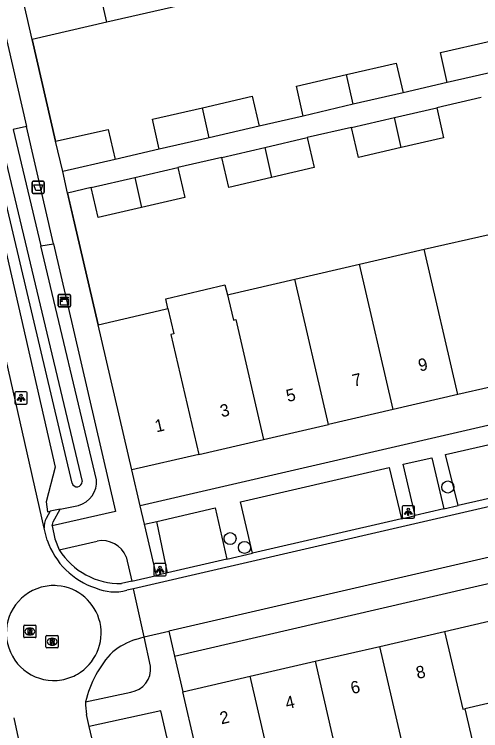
# Model space of a CAD drawing. Extents: x 156414 to 157775, y 382335 to 383765.
# Drawn here: x 156749.8 to 156787.7, y 382552.8 to 382611 of the extents above; entities that cross this region are included whole.
import ezdxf

# ---------------------------------------------------------------- set-up
doc = ezdxf.new("R2010")
doc.units = 0
for name, color, linetype in [('IMGEO_Afvalbak', 7, 'Continuous'), ('IMGEO_Berm_groen', 7, 'Continuous'), ('IMGEO_Boom', 7, 'Continuous'), ('IMGEO_Greppel_droge_sloot', 7, 'Continuous'), ('IMGEO_Haag', 7, 'Continuous'), ('IMGEO_Kast', 7, 'Continuous'), ('IMGEO_Lichtpunt', 7, 'Continuous'), ('IMGEO_Muur', 7, 'Continuous'), ('IMGEO_Pand', 7, 'Continuous'), ('IMGEO_Pand_nummerreeks', 7, 'Continuous'), ('IMGEO_Rijbaan_lokaal_gesloten', 7, 'Continuous'), ('IMGEO_Rijbaan_lokaal_open', 7, 'Continuous'), ('IMGEO_Rioolput', 7, 'Continuous'), ('IMGEO_Voetpad_open', 7, 'Continuous')]:
    doc.layers.add(name, color=color, linetype=linetype)

msp = doc.modelspace()

# ---------------------------------------------------------------- linework, layer by layer
at = {"layer": 'IMGEO_Afvalbak'}
for p, q in [((156751.392, 382597.403), (156752.182, 382597.403)), ((156752.182, 382597.403), (156751.392, 382597.403)), ((156751.292, 382596.503), (156751.292, 382597.303)), ((156751.292, 382597.303), (156751.292, 382596.503)), ((156752.282, 382597.303), (156752.282, 382596.503)), ((156752.282, 382596.503), (156752.282, 382597.303)), ((156752.182, 382596.403), (156751.392, 382596.403)), ((156751.392, 382596.403), (156752.182, 382596.403))]:
    msp.add_line(p, q, dxfattribs=at)
msp.add_lwpolyline([(156751.435, 382597.117), (156752.139, 382597.117), (156751.99, 382596.647), (156751.584, 382596.647), (156751.435, 382597.117)], dxfattribs=at)
for centre, start, end in [((156751.392, 382597.303), 90, 180), ((156751.392, 382597.303), 90, 180), ((156752.182, 382597.303), 0, 90), ((156752.182, 382597.303), 360, 90), ((156751.392, 382596.503), 180, 270), ((156751.392, 382596.503), 180, 270), ((156752.182, 382596.503), 270, 0), ((156752.182, 382596.503), 270, 0)]:
    msp.add_arc(centre, 0.1, start, end, dxfattribs=at)
at = {"layer": 'IMGEO_Berm_groen'}
for points in [[(156742.922, 382618.934), (156753.154, 382574.176), (156752.429, 382571.339), (156752.537, 382570.534), (156752.762, 382570.58)], [(156756.533, 382573.152), (156752.001, 382592.15)], [(156753.579, 382570.748), (156755.068, 382571.054)]]:
    msp.add_lwpolyline(points, dxfattribs=at)
msp.add_arc((156754.477, 382573.027), 2.059, 286.66477, 3.48327, dxfattribs=at)
at = {"layer": 'IMGEO_Boom'}
for centre in [(156785.07, 382572.555), (156767.379, 382568.36), (156768.551, 382567.646)]:
    msp.add_circle(centre, 0.489, dxfattribs=at)
at = {"layer": 'IMGEO_Greppel_droge_sloot'}
for points in [[(156754.54, 382572.878), (156743.906, 382617.872)], [(156744.672, 382617.996), (156748.601, 382601.316), (156750.852, 382591.876), (156755.355, 382572.999)]]:
    msp.add_lwpolyline(points, dxfattribs=at)
msp.add_arc((156754.94, 382572.988), 0.415, 195.34481, 1.54479, dxfattribs=at)
at = {"layer": 'IMGEO_Haag'}
for points in [[(156750.838, 382601.836), (156749.75, 382601.59)], [(156749.75, 382601.59), (156752.001, 382592.15)], [(156752.001, 382592.15), (156753.038, 382592.306)]]:
    msp.add_lwpolyline(points, dxfattribs=at)
at = {"layer": 'IMGEO_Kast'}
for p, q in [((156753.418, 382587.273), (156753.418, 382588.114)), ((156753.418, 382588.114), (156753.418, 382587.273)), ((156753.493, 382588.198), (156754.334, 382588.198)), ((156754.334, 382588.198), (156753.493, 382588.198)), ((156754.418, 382588.123), (156754.418, 382587.282)), ((156754.418, 382587.282), (156754.418, 382588.123)), ((156754.343, 382587.198), (156753.502, 382587.198)), ((156753.502, 382587.198), (156754.343, 382587.198))]:
    msp.add_line(p, q, dxfattribs=at)
for points in [[(156753.613, 382587.988), (156754.213, 382587.988), (156754.213, 382587.903), (156753.613, 382587.903), (156753.613, 382587.988)], [(156753.613, 382587.813), (156754.213, 382587.813), (156754.213, 382587.324), (156753.613, 382587.324), (156753.613, 382587.813)]]:
    msp.add_lwpolyline(points, dxfattribs=at)
msp.add_circle((156753.697, 382587.662), 0.0377, dxfattribs=at)
for centre, start, end in [((156753.496, 382588.12), 92.4484, 184.28452), ((156753.496, 382588.12), 92.4484, 184.28452), ((156754.34, 382588.12), 2.4484, 94.28452), ((156754.34, 382588.12), 2.4484, 94.28452), ((156753.496, 382587.276), 182.4484, 274.28452), ((156753.496, 382587.276), 182.4484, 274.28452), ((156754.34, 382587.276), 272.4484, 4.28452), ((156754.34, 382587.276), 272.4484, 4.28452)]:
    msp.add_arc(centre, 0.0779, start, end, dxfattribs=at)
at = {"layer": 'IMGEO_Lichtpunt'}
for p, q in [((156749.883, 382580.198), (156749.883, 382579.391)), ((156749.883, 382580.198), (156749.883, 382579.391)), ((156750.785, 382580.293), (156749.977, 382580.293)), ((156750.785, 382580.293), (156749.977, 382580.293)), ((156750.879, 382579.391), (156750.879, 382580.198)), ((156750.879, 382579.391), (156750.879, 382580.198)), ((156749.977, 382579.297), (156750.785, 382579.297)), ((156749.977, 382579.297), (156750.785, 382579.297)), ((156781.352, 382570.938), (156781.352, 382570.131)), ((156781.352, 382570.938), (156781.352, 382570.131)), ((156782.254, 382571.033), (156781.446, 382571.033)), ((156782.254, 382571.033), (156781.446, 382571.033)), ((156782.348, 382570.131), (156782.348, 382570.938)), ((156782.348, 382570.131), (156782.348, 382570.938)), ((156781.446, 382570.037), (156782.254, 382570.037)), ((156781.446, 382570.037), (156782.254, 382570.037)), ((156761.191, 382566.233), (156761.191, 382565.426)), ((156761.191, 382566.233), (156761.191, 382565.426)), ((156762.093, 382566.328), (156761.285, 382566.328)), ((156762.093, 382566.328), (156761.285, 382566.328)), ((156762.187, 382565.426), (156762.187, 382566.233)), ((156762.187, 382565.426), (156762.187, 382566.233)), ((156761.285, 382565.332), (156762.093, 382565.332)), ((156761.285, 382565.332), (156762.093, 382565.332))]:
    msp.add_line(p, q, dxfattribs=at)
for points in [[(156750.257, 382579.862), (156750.296, 382579.834), (156750.108, 382579.572), (156750.07, 382579.599), (156750.257, 382579.862)], [(156750.469, 382579.834), (156750.507, 382579.861), (156750.694, 382579.599), (156750.655, 382579.571), (156750.469, 382579.834)], [(156750.359, 382579.814), (156750.406, 382579.814), (156750.406, 382579.492), (156750.359, 382579.492), (156750.359, 382579.814)], [(156781.726, 382570.602), (156781.765, 382570.574), (156781.577, 382570.312), (156781.539, 382570.339), (156781.726, 382570.602)], [(156781.828, 382570.554), (156781.875, 382570.554), (156781.875, 382570.232), (156781.828, 382570.232), (156781.828, 382570.554)], [(156781.938, 382570.574), (156781.976, 382570.601), (156782.163, 382570.339), (156782.124, 382570.311), (156781.938, 382570.574)], [(156761.565, 382565.897), (156761.604, 382565.869), (156761.416, 382565.607), (156761.378, 382565.634), (156761.565, 382565.897)], [(156761.777, 382565.869), (156761.815, 382565.896), (156762.002, 382565.634), (156761.963, 382565.606), (156761.777, 382565.869)], [(156761.667, 382565.849), (156761.714, 382565.849), (156761.714, 382565.527), (156761.667, 382565.527), (156761.667, 382565.849)]]:
    msp.add_lwpolyline(points, dxfattribs=at)
for centre in [(156750.382, 382579.996), (156781.851, 382570.736), (156761.69, 382566.031)]:
    msp.add_circle(centre, 0.0994, dxfattribs=at)
for centre, start, end in [((156749.977, 382580.198), 90, 180), ((156749.977, 382580.198), 90, 180), ((156750.785, 382580.198), 0, 90), ((156750.785, 382580.198), 0, 90), ((156749.977, 382579.391), 180, 270), ((156749.977, 382579.391), 180, 270), ((156750.785, 382579.391), 270, 0), ((156750.785, 382579.391), 270, 360), ((156781.446, 382570.938), 90, 180), ((156781.446, 382570.938), 90, 180), ((156782.254, 382570.938), 0, 90), ((156782.254, 382570.938), 0, 90), ((156781.446, 382570.131), 180, 270), ((156781.446, 382570.131), 180, 270), ((156782.254, 382570.131), 270, 0), ((156782.254, 382570.131), 270, 360), ((156761.285, 382566.233), 90, 180), ((156761.285, 382566.233), 90, 180), ((156762.093, 382566.233), 0, 90), ((156762.093, 382566.233), 0, 90), ((156761.285, 382565.426), 180, 270), ((156761.285, 382565.426), 180, 270), ((156762.093, 382565.426), 270, 0), ((156762.093, 382565.426), 270, 360)]:
    msp.add_arc(centre, 0.0946, start, end, dxfattribs=at)
at = {"layer": 'IMGEO_Muur'}
for points in [[(156751.301, 382608.917), (156753.206, 382600.657)], [(156754.739, 382594), (156754.172, 382596.455)], [(156756.65, 382585.734), (156754.739, 382594)]]:
    msp.add_lwpolyline(points, dxfattribs=at)
at = {"layer": 'IMGEO_Pand'}
for points in [[(156751.301, 382608.917), (156747.906, 382623.621)], [(156757.366, 382610.315), (156754.657, 382622.088)], [(156763.216, 382611.663), (156757.366, 382610.315)], [(156757.366, 382610.315), (156751.301, 382608.917)], [(156785.022, 382605.412), (156784.459, 382607.848), (156788.515, 382608.786)], [(156776.837, 382606.076), (156780.864, 382607.006), (156781.434, 382604.572)], [(156773.325, 382602.699), (156772.762, 382605.135), (156776.837, 382606.076)], [(156777.379, 382603.65), (156776.837, 382606.076)], [(156789.066, 382606.348), (156785.022, 382605.412)], [(156765.136, 382603.374), (156769.174, 382604.304), (156769.738, 382601.869)], [(156781.434, 382604.572), (156777.379, 382603.65)], [(156761.629, 382600), (156761.068, 382602.436), (156765.136, 382603.374)], [(156765.677, 382600.933), (156765.136, 382603.374)], [(156777.379, 382603.65), (156773.325, 382602.699)], [(156780.723, 382602.572), (156784.164, 382603.368)], [(156784.164, 382603.368), (156784.72, 382600.931), (156781.268, 382600.132)], [(156777.243, 382601.766), (156780.723, 382602.572)], [(156781.268, 382600.132), (156780.723, 382602.572)], [(156753.206, 382600.657), (156757.462, 382601.592), (156758.032, 382599.158)], [(156769.738, 382601.869), (156765.677, 382600.933)], [(156781.268, 382600.132), (156777.807, 382599.331), (156777.243, 382601.766)], [(156765.677, 382600.933), (156761.629, 382600)], [(156770.19, 382600.141), (156773.639, 382600.94)], [(156773.639, 382600.94), (156774.198, 382598.503), (156770.736, 382597.701)], [(156753.785, 382598.18), (156753.206, 382600.657)], [(156766.717, 382599.337), (156770.19, 382600.141)], [(156770.19, 382600.141), (156770.736, 382597.701)], [(156758.032, 382599.158), (156753.785, 382598.18)], [(156770.736, 382597.701), (156767.281, 382596.901), (156766.717, 382599.337)], [(156759.63, 382597.697), (156763.126, 382598.503)], [(156763.126, 382598.503), (156763.691, 382596.068), (156760.177, 382595.258)], [(156756.097, 382596.883), (156759.63, 382597.697)], [(156759.63, 382597.697), (156760.177, 382595.258)], [(156760.177, 382595.258), (156756.658, 382594.447), (156756.097, 382596.883)], [(156783.154, 382591.87), (156788.417, 382593.085)], [(156777.894, 382590.654), (156783.154, 382591.87)], [(156785.883, 382580.062), (156783.154, 382591.87)], [(156772.632, 382589.438), (156777.894, 382590.654)], [(156780.621, 382578.847), (156777.894, 382590.654)], [(156767.174, 382588.177), (156767.381, 382588.225), (156772.632, 382589.438)], [(156775.36, 382577.632), (156772.632, 382589.438)], [(156762.333, 382587.053), (156762.147, 382587.853), (156766.962, 382588.971), (156767.174, 382588.177)], [(156767.174, 382588.177), (156767.259, 382587.811), (156767.651, 382586.122), (156767.854, 382586.169), (156770.098, 382576.416)], [(156756.65, 382585.734), (156762.096, 382586.998), (156762.333, 382587.053)], [(156762.333, 382587.053), (156762.81, 382584.998), (156762.573, 382584.943), (156764.837, 382575.201)], [(156759.384, 382573.942), (156756.65, 382585.734)], [(156791.144, 382581.277), (156785.883, 382580.062)], [(156785.883, 382580.062), (156780.621, 382578.847)], [(156780.621, 382578.847), (156775.36, 382577.632)], [(156770.098, 382576.416), (156775.36, 382577.632)], [(156764.837, 382575.201), (156770.098, 382576.416)], [(156764.837, 382575.201), (156759.384, 382573.942)], [(156784.802, 382560.825), (156794.554, 382563.08)], [(156779.539, 382559.608), (156784.802, 382560.825)], [(156784.802, 382560.825), (156786.273, 382554.495), (156786.454, 382554.537)], [(156774.288, 382558.394), (156779.539, 382559.608)], [(156782.269, 382547.821), (156779.539, 382559.608)], [(156769.007, 382557.173), (156774.288, 382558.394)], [(156774.288, 382558.394), (156776.998, 382546.602)], [(156763.544, 382555.909), (156769.007, 382557.173)], [(156771.884, 382545.42), (156771.744, 382545.387), (156769.007, 382557.173)], [(156796.007, 382556.747), (156786.454, 382554.537)], [(156766.55, 382542.92), (156763.544, 382555.909)], [(156786.454, 382554.537), (156787.716, 382549.081), (156787.541, 382549.041), (156782.269, 382547.821)]]:
    msp.add_lwpolyline(points, dxfattribs=at)
at = {"layer": 'IMGEO_Rijbaan_lokaal_gesloten'}
for points in [[(156752.281, 382569.222), (156746.207, 382595.976), (156740.355, 382620.711)], [(156847.074, 382584.513), (156759.529, 382564.293)], [(156846.459, 382580.188), (156845.95, 382580.133), (156762.402, 382560.842)], [(156752.529, 382568.229), (156752.281, 382569.222)], [(156759.529, 382564.293), (156758.977, 382564.166)], [(156760.387, 382560.376), (156759.529, 382564.293)], [(156760.387, 382560.376), (156762.402, 382560.842)], [(156759.684, 382560.167), (156760.387, 382560.376)], [(156749.814, 382553.79), (156750.255, 382551.783)], [(156755.942, 382553.09), (156755.709, 382554.074)], [(156769.196, 382497.794), (156768.84, 382497.586), (156763.253, 382522.164), (156755.942, 382553.09)]]:
    msp.add_lwpolyline(points, dxfattribs=at)
for centre, radius, start, end in [((156758.355, 382570.202), 6.151, 198.70456, 251.98583), ((156757.977, 382567.82), 3.788, 246.27217, 285.29852), ((156761.745, 382554.189), 6.324, 109.0215, 128.0551), ((156763.983, 382553.196), 8.563, 135.7759, 167.1788), ((156762.73, 382555.103), 7.096, 180.05619, 188.33812)]:
    msp.add_arc(centre, radius, start, end, dxfattribs=at)
at = {"layer": 'IMGEO_Rijbaan_lokaal_open'}
for points in [[(156790.817, 382572.176), (156785.914, 382571.042)], [(156752.762, 382570.58), (156752.44, 382570.006)], [(156753.579, 382570.748), (156752.762, 382570.58)], [(156752.92, 382569.406), (156753, 382569.721), (156753.579, 382570.748)], [(156784.743, 382570.771), (156782.406, 382570.23)], [(156784.743, 382570.771), (156785.914, 382571.042)], [(156781.292, 382569.972), (156769.209, 382567.177)], [(156781.292, 382569.972), (156782.406, 382570.23)], [(156752.92, 382569.406), (156753.14, 382568.35), (156753.503, 382567.451)], [(156767.11, 382566.691), (156769.209, 382567.177)], [(156767.11, 382566.691), (156762.299, 382565.578)], [(156759.395, 382564.903), (156761.408, 382565.372)], [(156762.299, 382565.578), (156761.408, 382565.372)], [(156759.395, 382564.903), (156758.561, 382564.725)]]:
    msp.add_lwpolyline(points, dxfattribs=at)
for centre, radius, start, end in [((156753.557, 382569.371), 1.285, 150.39968, 186.67144), ((156758.419, 382570.517), 5.794, 211.95221, 271.40306), ((156753.049, 382560.69), 3.854, 105.24517, 279.97224), ((156753.047, 382560.721), 3.824, 85.57877, 105.34741), ((156753.049, 382560.69), 3.855, 299.85198, 85.6442), ((156753.053, 382560.682), 3.846, 279.92354, 299.85884)]:
    msp.add_arc(centre, radius, start, end, dxfattribs=at)
at = {"layer": 'IMGEO_Rioolput'}
for p, q in [((156750.608, 382560.391), (156750.608, 382561.243)), ((156750.683, 382561.317), (156751.535, 382561.317)), ((156751.609, 382561.243), (156751.609, 382560.391)), ((156751.096, 382561.097), (156751.121, 382561.097)), ((156751.535, 382560.317), (156750.683, 382560.317)), ((156751.119, 382560.537), (156751.094, 382560.537)), ((156752.42, 382559.562), (156752.42, 382560.414)), ((156752.495, 382560.488), (156753.347, 382560.488)), ((156752.908, 382560.268), (156752.933, 382560.268)), ((156753.421, 382560.414), (156753.421, 382559.562)), ((156753.347, 382559.488), (156752.495, 382559.488)), ((156752.931, 382559.708), (156752.906, 382559.708))]:
    msp.add_line(p, q, dxfattribs=at)
for points in [[(156750.608, 382560.391), (156750.608, 382561.243)], [(156750.683, 382561.317), (156751.535, 382561.317)], [(156751.609, 382561.243), (156751.609, 382560.391)], [(156751.197, 382561.015), (156750.945, 382561.017), (156750.945, 382560.617)], [(156750.945, 382560.617), (156751.069, 382560.617), (156751.069, 382560.779), (156751.08, 382560.779)], [(156751.123, 382560.936), (156751.069, 382560.936), (156751.069, 382560.855)], [(156751.069, 382560.855), (156751.121, 382560.855)], [(156751.127, 382560.75), (156751.198, 382560.617), (156751.338, 382560.617), (156751.273, 382560.743)], [(156751.535, 382560.317), (156750.683, 382560.317)], [(156752.42, 382559.562), (156752.42, 382560.414)], [(156752.495, 382560.488), (156753.347, 382560.488)], [(156753.009, 382560.186), (156752.757, 382560.188), (156752.757, 382559.788)], [(156752.935, 382560.107), (156752.881, 382560.107), (156752.881, 382560.026)], [(156753.421, 382560.414), (156753.421, 382559.562)], [(156753.347, 382559.488), (156752.495, 382559.488)], [(156752.757, 382559.788), (156752.881, 382559.788), (156752.881, 382559.95), (156752.892, 382559.95)], [(156752.881, 382560.026), (156752.933, 382560.026)], [(156752.939, 382559.921), (156753.01, 382559.788), (156753.15, 382559.788), (156753.085, 382559.914)]]:
    msp.add_lwpolyline(points, dxfattribs=at)
for centre, radius, start, end in [((156750.685, 382561.241), 0.0765, 91.55205, 178.44795), ((156750.685, 382561.241), 0.0765, 91.55205, 178.44795), ((156751.533, 382561.241), 0.0765, 1.55205, 88.44795), ((156751.533, 382561.241), 0.0765, 1.55205, 88.44795), ((156751.079, 382560.726), 0.0533, 26.02933, 88.69889), ((156751.105, 382561.044), 0.19, 274.7715, 282.96867), ((156751.129, 382560.84), 0.0964, 77.00612, 93.18647), ((156751.143, 382560.897), 0.0378, 276.66336, 79.67722), ((156751.196, 382560.905), 0.109, 350.36119, 89.41601), ((156751.194, 382560.905), 0.112, 277.58423, 350.98172), ((156751.178, 382560.69), 0.108, 29.51342, 73.79051), ((156750.685, 382560.393), 0.0765, 181.55205, 268.44795), ((156750.685, 382560.393), 0.0765, 181.55205, 268.44795), ((156751.533, 382560.393), 0.0765, 271.55205, 358.44795), ((156751.533, 382560.393), 0.0765, 271.55205, 358.44795), ((156752.497, 382560.412), 0.0765, 91.55205, 178.44795), ((156752.497, 382560.412), 0.0765, 91.55205, 178.44795), ((156752.941, 382560.011), 0.0964, 77.00612, 93.18647), ((156752.955, 382560.068), 0.0378, 276.66336, 79.67722), ((156753.008, 382560.076), 0.109, 350.36119, 89.41601), ((156753.345, 382560.412), 0.0765, 1.55205, 88.44795), ((156753.345, 382560.412), 0.0765, 1.55205, 88.44795), ((156752.497, 382559.564), 0.0765, 181.55205, 268.44795), ((156752.497, 382559.564), 0.0765, 181.55205, 268.44795), ((156752.891, 382559.897), 0.0533, 26.02933, 88.69889), ((156752.917, 382560.215), 0.19, 274.7715, 282.96867), ((156753.006, 382560.076), 0.112, 277.58423, 350.98172), ((156752.99, 382559.861), 0.108, 29.51342, 73.79051), ((156753.345, 382559.564), 0.0765, 271.55205, 358.44795), ((156753.345, 382559.564), 0.0765, 271.55205, 358.44795)]:
    msp.add_arc(centre, radius, start, end, dxfattribs=at)
for centre, major_axis, ratio, start_param, end_param in [((156751.095, 382560.817), (-0.387, 0.002), 0.722429, 4.712389, 7.853982), ((156751.12, 382560.817), (-0.39, 0.002), 0.717154, 1.570796, 4.712389), ((156752.907, 382559.988), (-0.387, 0.002), 0.722429, 4.712389, 7.853982), ((156752.932, 382559.988), (-0.39, 0.002), 0.717154, 1.570796, 4.712389)]:
    msp.add_ellipse(centre, major_axis=major_axis, ratio=ratio, start_param=start_param, end_param=end_param, dxfattribs=at)
at = {"layer": 'IMGEO_Voetpad_open'}
for points in [[(156740.355, 382620.711), (156746.172, 382622.047), (156750.838, 382601.836)], [(156753.206, 382600.657), (156751.301, 382608.917)], [(156785.022, 382605.412), (156781.434, 382604.572)], [(156787.769, 382604.19), (156784.164, 382603.368)], [(156773.325, 382602.699), (156769.738, 382601.869)], [(156753.038, 382592.306), (156750.838, 382601.836)], [(156777.243, 382601.766), (156773.639, 382600.94)], [(156761.629, 382600), (156758.032, 382599.158)], [(156766.717, 382599.337), (156763.126, 382598.503)], [(156754.176, 382596.439), (156753.785, 382598.18)], [(156756.097, 382596.883), (156754.176, 382596.439)], [(156754.176, 382596.439), (156754.739, 382594), (156756.65, 382585.734)], [(156753.038, 382592.306), (156758.056, 382570.571), (156752.92, 382569.406)], [(156830.614, 382587.326), (156760.061, 382571.022)], [(156785.914, 382571.042), (156784.879, 382575.193), (156789.848, 382576.342), (156790.817, 382572.176)], [(156782.406, 382570.23), (156781.452, 382574.4), (156783.77, 382574.936), (156784.743, 382570.771)], [(156769.209, 382567.177), (156768.23, 382571.341), (156780.307, 382574.135), (156781.292, 382569.972)], [(156760.061, 382571.022), (156759.384, 382573.942)], [(156760.417, 382569.534), (156760.061, 382571.022)], [(156761.414, 382569.765), (156766.161, 382570.863), (156767.11, 382566.691)], [(156760.417, 382569.534), (156761.414, 382569.765)], [(156761.408, 382565.372), (156760.417, 382569.534)], [(156762.299, 382565.578), (156761.414, 382569.765)], [(156762.868, 382558.825), (156803.79, 382568.291)], [(156753.503, 382567.451), (156756.573, 382568.158)], [(156758.93, 382566.882), (156759.395, 382564.903)], [(156762.402, 382560.842), (156762.868, 382558.825)], [(156760.917, 382557.986), (156760.387, 382560.376)], [(156762.868, 382558.825), (156763.544, 382555.909)], [(156755.634, 382555.096), (156759.306, 382555.897)], [(156767.799, 382528.265), (156761.759, 382554.359), (156755.942, 382553.09)]]:
    msp.add_lwpolyline(points, dxfattribs=at)
for centre, radius, start, end in [((156756.98, 382566.094), 2.104, 21.99643, 101.14434), ((156759.035, 382557.772), 1.894, 278.22469, 6.49775)]:
    msp.add_arc(centre, radius, start, end, dxfattribs=at)

# ---------------------------------------------------------------- texts
at = {"layer": 'IMGEO_Pand_nummerreeks'}
for s, rotation, p in [('9', 13.00773, (156782.789, 382581.933)), ('7', 13.00773, (156777.424, 382580.694)), ('5', 13.00614, (156772.057, 382579.454)), ('3', 13.00614, (156766.689, 382578.214)), ('1', 12.99006, (156761.387, 382576.99)), ('8', 13.01139, (156782.608, 382556.948)), ('6', 13.01139, (156777.294, 382555.72)), ('4', 13.01139, (156771.983, 382554.493)), ('2', 13.01139, (156766.667, 382553.265))]:
    msp.add_text(s, height=1, rotation=rotation, dxfattribs=at).set_placement(p)

doc.saveas('drawing.dxf')
